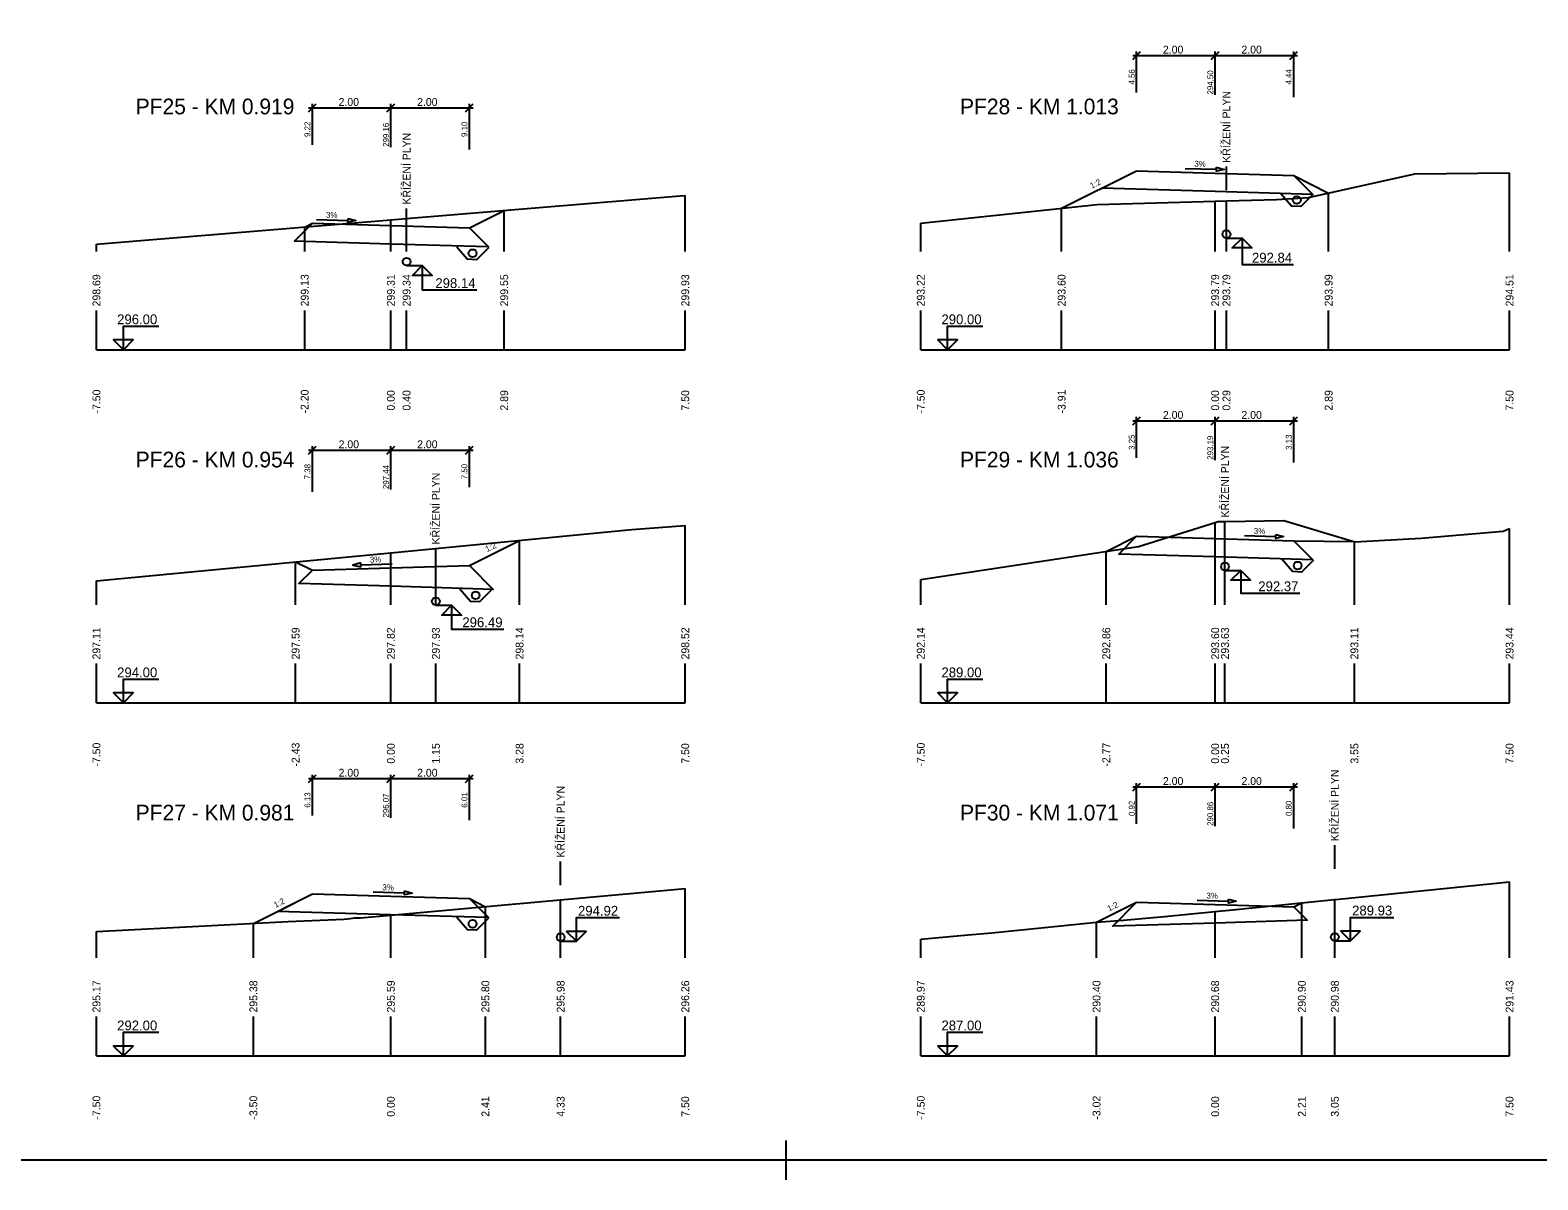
# Model space of a CAD drawing. Extents: x -9 to 2311, y -2 to 597.
# Drawn here: x 1693.1 to 2077.2, y -1.6 to 291.5 of the extents above; entities that cross this region are included whole.
import ezdxf

# ---------------------------------------------------------------- set-up
doc = ezdxf.new("R2010")
doc.units = 0
for name, color, linetype in [('KOTA', 7, 'Continuous'), ('KOTA_DELKY', 7, 'Continuous'), ('KOTA_DELKY_CONT', 7, 'Continuous'), ('KRIZENI', 7, 'Continuous'), ('NS_TELESO_VOZOVKY', 7, 'Continuous'), ('NS_V_PF', 7, 'Continuous'), ('POPISY_NAD_TERENEM', 7, 'Continuous'), ('REZY_PF_PUVODNI', 7, 'Continuous'), ('SESTAVY_REZU_PF', 7, 'Continuous'), ('SKLON', 7, 'Continuous'), ('SVK', 7, 'Continuous'), ('SVK_STAT', 7, 'Continuous')]:
    doc.layers.add(name, color=color, linetype=linetype)

msp = doc.modelspace()

# ---------------------------------------------------------------- linework, layer by layer
for p, q in [((1885.65, 8.39), (1885.65, -1.61)), ((1885.65, 8.39), (1885.65, -1.61)), ((1885.65, 8.39), (1885.65, -1.61)), ((1885.65, 8.39), (1885.65, -1.61)), ((1885.65, 8.39), (1885.65, -1.61)), ((1885.65, 8.39), (1885.65, -1.61)), ((1885.65, 8.39), (1885.65, -1.61)), ((1885.65, 8.39), (1885.65, -1.61)), ((1885.65, 8.39), (1885.65, -1.61)), ((1885.65, 8.39), (1885.65, -1.61)), ((1885.65, 8.39), (1885.65, -1.61)), ((1885.65, 8.39), (1885.65, -1.61)), ((1890.65, 3.39), (1880.65, 3.39)), ((1890.65, 3.39), (1880.65, 3.39)), ((1890.65, 3.39), (1880.65, 3.39)), ((1890.65, 3.39), (1880.65, 3.39)), ((1890.65, 3.39), (1880.65, 3.39)), ((1890.65, 3.39), (1880.65, 3.39)), ((1890.65, 3.39), (1880.65, 3.39)), ((1890.65, 3.39), (1880.65, 3.39)), ((1890.65, 3.39), (1880.65, 3.39)), ((1890.65, 3.39), (1880.65, 3.39)), ((1890.65, 3.39), (1880.65, 3.39)), ((1890.65, 3.39), (1880.65, 3.39))]:
    msp.add_line(p, q)
msp.add_lwpolyline([(-4.35, 597.39), (2305.65, 597.39), (2305.65, 3.39), (-4.35, 3.39)], close=True)
for points in [[(2019.85, 249.55), (2016.79, 246.51), (2014.45, 246.61), (2011.74, 249.75)], [(1809.88, 235.98), (1806.83, 232.94), (1804.48, 233.04), (1801.77, 236.18)], [(2020.07, 156.37), (2017.02, 153.33), (2014.67, 153.43), (2011.97, 156.57)], [(1810.66, 148.8), (1807.61, 145.76), (1805.26, 145.86), (1802.55, 149)], [(1809.89, 65.06), (1806.84, 62.03), (1804.49, 62.13), (1801.78, 65.26)]]:
    msp.add_lwpolyline(points)
for centre in [(2015.79, 248.15), (1805.82, 234.58), (2016.01, 154.97), (1806.6, 147.39), (1805.83, 63.66)]:
    msp.add_circle(centre, 1)
at = {"layer": 'KOTA'}
for points in [[(1997.87, 238.44), (2001.87, 238.44), (2004.37, 235.94), (2001.87, 235.94)], [(2001.87, 235.94), (1999.37, 235.94), (2001.87, 238.44), (2001.87, 231.71), (2014.96, 231.71)], [(1789.01, 231.44), (1793.01, 231.44), (1795.51, 228.94), (1793.01, 228.94)], [(1793.01, 228.94), (1790.51, 228.94), (1793.01, 231.44), (1793.01, 225.22), (1806.93, 225.22)], [(1716.85, 212.5), (1714.35, 212.5), (1716.85, 210), (1716.85, 216), (1725.85, 216)], [(1926.85, 212.5), (1924.35, 212.5), (1926.85, 210), (1926.85, 216), (1935.85, 216)], [(1716.85, 210), (1719.35, 212.5), (1716.85, 212.5)], [(1926.85, 210), (1929.35, 212.5), (1926.85, 212.5)], [(1997.5, 153.72), (2001.5, 153.72), (2004, 151.22), (2001.5, 151.22)], [(2001.5, 151.22), (1999, 151.22), (2001.5, 153.72), (2001.5, 147.95), (2016.58, 147.95)], [(1796.46, 144.86), (1800.46, 144.86), (1802.96, 142.36), (1800.46, 142.36)], [(1800.46, 142.36), (1797.96, 142.36), (1800.46, 144.86), (1800.46, 138.77), (1813.81, 138.77)], [(1716.85, 122.5), (1714.35, 122.5), (1716.85, 120), (1716.85, 126), (1725.85, 126)], [(1926.85, 122.5), (1924.35, 122.5), (1926.85, 120), (1926.85, 126), (1935.85, 126)], [(1716.85, 120), (1719.35, 122.5), (1716.85, 122.5)], [(1926.85, 120), (1929.35, 122.5), (1926.85, 122.5)], [(2029.48, 61.8), (2026.98, 61.8), (2029.48, 59.3), (2029.48, 65.3), (2040.48, 65.3)], [(2029.48, 61.8), (2026.98, 61.8), (2029.48, 59.3), (2029.48, 65.3), (2040.48, 65.3)], [(1828.26, 59.23), (1832.26, 59.23), (1834.76, 61.73), (1832.26, 61.73)], [(1828.26, 59.23), (1832.26, 59.23), (1834.76, 61.73), (1832.26, 61.73)], [(1832.26, 61.73), (1829.76, 61.73), (1832.26, 59.23), (1832.26, 65.23), (1843.26, 65.23)], [(1832.26, 61.73), (1829.76, 61.73), (1832.26, 59.23), (1832.26, 65.23), (1843.26, 65.23)], [(2025.48, 59.3), (2029.48, 59.3), (2031.98, 61.8), (2029.48, 61.8)], [(2025.48, 59.3), (2029.48, 59.3), (2031.98, 61.8), (2029.48, 61.8)], [(1716.85, 32.5), (1714.35, 32.5), (1716.85, 30), (1716.85, 36), (1725.85, 36)], [(1926.85, 32.5), (1924.35, 32.5), (1926.85, 30), (1926.85, 36), (1935.85, 36)], [(1716.85, 30), (1719.35, 32.5), (1716.85, 32.5)], [(1926.85, 30), (1929.35, 32.5), (1926.85, 32.5)]]:
    msp.add_lwpolyline(points, dxfattribs=at)
at = {"layer": 'KOTA_DELKY'}
for points in [[(1974, 284), (1976, 286)], [(1974, 285), (1996, 285)], [(1975, 275.6), (1975, 286)], [(1994, 284), (1996, 286)], [(1994, 284), (1996, 286)], [(1994, 285), (2016, 285)], [(1995, 275), (1995, 286)], [(1995, 275), (1995, 286)], [(2014, 284), (2016, 286)], [(2015, 274.4), (2015, 286)], [(1764, 270.64), (1766, 272.64)], [(1764, 271.64), (1786, 271.64)], [(1765, 262.24), (1765, 272.64)], [(1784, 270.64), (1786, 272.64)], [(1784, 270.64), (1786, 272.64)], [(1784, 271.64), (1806, 271.64)], [(1785, 261.64), (1785, 272.64)], [(1785, 261.64), (1785, 272.64)], [(1804, 270.64), (1806, 272.64)], [(1805, 261.04), (1805, 272.64)], [(1974, 190.88), (1976, 192.88)], [(1975, 182.48), (1975, 192.88)], [(1994, 190.88), (1996, 192.88)], [(1994, 190.88), (1996, 192.88)], [(1995, 181.88), (1995, 192.88)], [(1995, 181.88), (1995, 192.88)], [(2014, 190.88), (2016, 192.88)], [(2015, 181.28), (2015, 192.88)], [(1974, 191.88), (1996, 191.88)], [(1994, 191.88), (2016, 191.88)], [(1764, 183.39), (1766, 185.39)], [(1764, 184.39), (1786, 184.39)], [(1765, 173.79), (1765, 185.39)], [(1784, 183.39), (1786, 185.39)], [(1784, 183.39), (1786, 185.39)], [(1784, 184.39), (1806, 184.39)], [(1785, 174.39), (1785, 185.39)], [(1785, 174.39), (1785, 185.39)], [(1804, 183.39), (1806, 185.39)], [(1805, 174.99), (1805, 185.39)], [(1764, 99.67), (1766, 101.67)], [(1764, 100.67), (1786, 100.67)], [(1765, 91.27), (1765, 101.67)], [(1784, 99.67), (1786, 101.67)], [(1784, 99.67), (1786, 101.67)], [(1784, 100.67), (1806, 100.67)], [(1785, 90.67), (1785, 101.67)], [(1785, 90.67), (1785, 101.67)], [(1804, 99.67), (1806, 101.67)], [(1805, 90.07), (1805, 101.67)], [(1974, 97.55), (1976, 99.55)], [(1974, 98.55), (1996, 98.55)], [(1975, 89.15), (1975, 99.55)], [(1994, 97.55), (1996, 99.55)], [(1994, 97.55), (1996, 99.55)], [(1994, 98.55), (2016, 98.55)], [(1995, 88.55), (1995, 99.55)], [(1995, 88.55), (1995, 99.55)], [(2014, 97.55), (2016, 99.55)], [(2015, 87.95), (2015, 99.55)]]:
    msp.add_lwpolyline(points, dxfattribs=at)
at = {"layer": 'KRIZENI'}
for centre in [(1997.87, 239.44), (1789.01, 232.44), (1997.5, 154.72), (1796.46, 145.86), (1828.26, 60.23), (2025.48, 60.3)]:
    msp.add_circle(centre, 1, dxfattribs=at)
at = {"layer": 'NS_TELESO_VOZOVKY'}
for points in [[(1995, 255), (2015, 254.4), (2015, 254.4), (2019.85, 249.55), (1995, 250.3), (1966.13, 251.16), (1975, 255.6), (1975, 255.6), (1995, 255)], [(1785, 241.64), (1805, 241.04), (1805, 241.04), (1809.85, 236.2), (1785, 236.94), (1760.44, 237.68), (1765, 242.24), (1765, 242.24), (1785, 241.64)], [(1995, 161.88), (2015, 161.28), (2015, 161.28), (2019.85, 156.43), (1995, 157.18), (1970.44, 157.91), (1975, 162.48), (1975, 162.48), (1995, 161.88)], [(1785, 154.39), (1805, 154.99), (1805, 154.99), (1811.08, 148.91), (1785, 149.69), (1761.6, 150.39), (1765, 153.79), (1765, 153.79), (1785, 154.39)], [(1785, 70.67), (1805, 70.07), (1805, 70.07), (1809.85, 65.23), (1785, 65.97), (1756.13, 66.84), (1765, 71.27), (1765, 71.27), (1785, 70.67)], [(1995, 68.55), (2015, 67.95), (2015, 67.95), (2018.4, 64.56), (1995, 63.85), (1968.92, 63.07), (1975, 69.15), (1975, 69.15), (1995, 68.55)]]:
    msp.add_lwpolyline(points, dxfattribs=at)
at = {"layer": 'NS_V_PF'}
for points in [[(1955.88, 246.04), (1975, 255.6), (1975, 255.6), (1995, 255), (2015, 254.4), (2015, 254.4), (2023.91, 249.94)], [(1763.05, 241.27), (1765, 242.24), (1765, 242.24), (1785, 241.64), (1805, 241.04), (1805, 241.04), (1813.88, 245.48)], [(1760.73, 155.93), (1765, 153.79), (1765, 153.79), (1785, 154.39), (1805, 154.99), (1805, 154.99), (1817.79, 161.39)], [(1967.26, 158.6), (1975, 162.48), (1975, 162.48), (1995, 161.88), (2015, 161.28), (2015, 161.28), (2030.47, 161.07)], [(1749.98, 63.76), (1765, 71.27), (1765, 71.27), (1785, 70.67), (1805, 70.07), (1805, 70.07), (1809.09, 68.02)], [(1964.78, 64.04), (1975, 69.15), (1975, 69.15), (1995, 68.55), (2015, 67.95), (2015, 67.95), (2017.07, 68.99)]]:
    msp.add_lwpolyline(points, dxfattribs=at)
at = {"layer": 'POPISY_NAD_TERENEM'}
for points in [[(1997.87, 250.67), (1997.87, 256.67)], [(1789.01, 240), (1789.01, 246)], [(1997.5, 160.21), (1997.5, 166.21)], [(1796.46, 153.38), (1796.46, 159.38)], [(2025.48, 77.71), (2025.48, 83.71)], [(1828.26, 73.53), (1828.26, 79.53)]]:
    msp.add_lwpolyline(points, dxfattribs=at)
at = {"layer": 'REZY_PF_PUVODNI'}
for points in [[(1920, 242.22), (1964.95, 247), (1995, 247.86), (1997.85, 247.94), (2010.66, 248.31), (2018.79, 248.81), (2045.87, 254.8), (2070, 255.1)], [(1710, 236.87), (1785, 243.09), (1785, 243.09), (1788.93, 243.41), (1858.69, 249.2), (1860, 249.31)], [(1710, 151.07), (1785, 158.25), (1785, 158.25), (1796.34, 159.33), (1846.41, 164.13), (1860, 165.22)], [(1920, 151.42), (1975.45, 159.85), (1995, 165.99), (1995.73, 166.22), (1997.74, 166.25), (2012.51, 166.5), (2030.59, 161.04), (2047.52, 162), (2068.34, 163.77), (2070, 164.44)], [(1920, 59.71), (1925.51, 60.22), (1932.04, 60.83), (1938.14, 61.4), (1951.48, 62.72), (1964.8, 64.04), (1971.66, 64.62), (1982.09, 65.49), (1995, 66.78), (1995, 66.78), (1995.78, 66.86), (1998.55, 67.14), (2025.42, 69.82), (2026.47, 69.93), (2070, 74.33)], [(1710, 61.68), (1758.82, 64.22), (1773.1, 64.85), (1774.62, 65.01), (1775.79, 65.16), (1777.3, 65.17), (1785, 65.85), (1785, 65.85), (1785.01, 65.85), (1828.14, 69.74), (1860, 72.62)]]:
    msp.add_lwpolyline(points, dxfattribs=at)
at = {"layer": 'SESTAVY_REZU_PF'}
for points in [[(1710, 210), (1860, 210)], [(1920, 210), (2070, 210)], [(1710, 120), (1860, 120)], [(1920, 120), (2070, 120)], [(1710, 30), (1860, 30)], [(1920, 30), (2070, 30)]]:
    msp.add_lwpolyline(points, dxfattribs=at)
at = {"layer": 'SKLON'}
for points in [[(1987.32, 256.23), (1995.31, 255.99)], [(1995.33, 256.49), (1997.31, 255.93), (1995.3, 255.49), (1995.33, 256.49)], [(1766.09, 243.21), (1774.09, 242.97)], [(1774.1, 243.47), (1776.09, 242.91), (1774.07, 242.47), (1774.1, 243.47)], [(2002.45, 162.65), (2010.45, 162.41)], [(2010.47, 162.91), (2012.45, 162.35), (2010.44, 161.91), (2010.47, 162.91)], [(1777.32, 155.66), (1775.33, 155.1), (1777.35, 154.66), (1777.32, 155.66)], [(1777.33, 155.16), (1785.33, 155.4)], [(1780.47, 71.81), (1788.47, 71.57)], [(1788.48, 72.07), (1790.47, 71.51), (1788.45, 71.07), (1788.48, 72.07)], [(1990.38, 69.69), (1998.38, 69.45)], [(1998.39, 69.95), (2000.38, 69.39), (1998.36, 68.95), (1998.39, 69.95)]]:
    msp.add_lwpolyline(points, dxfattribs=at)
at = {"layer": 'SVK'}
for points in [[(2070, 235), (2070, 255.1)], [(2023.91, 235), (2023.91, 249.94)], [(1860, 235), (1860, 249.31)], [(1955.88, 235), (1955.88, 246.04)], [(1995, 235), (1995, 247.86)], [(1785, 235), (1785, 243.09)], [(1813.88, 235), (1813.88, 245.48)], [(1920, 235), (1920, 242.22)], [(1763.05, 235), (1763.05, 241.27)], [(1710, 235), (1710, 236.87)], [(1710, 210), (1710, 220)], [(1763.05, 210), (1763.05, 220)], [(1785, 210), (1785, 220)], [(1813.88, 210), (1813.88, 220)], [(1860, 210), (1860, 220)], [(1920, 210), (1920, 220)], [(1955.88, 210), (1955.88, 220)], [(1995, 210), (1995, 220)], [(2023.91, 210), (2023.91, 220)], [(2070, 210), (2070, 220)], [(1860, 145), (1860, 165.22)], [(1995, 145), (1995, 165.99)], [(1817.79, 145), (1817.79, 161.39)], [(2070, 145), (2070, 164.44)], [(1785, 145), (1785, 158.25)], [(1967.26, 145), (1967.26, 158.6)], [(2030.47, 145), (2030.47, 161.07)], [(1760.73, 145), (1760.73, 155.93)], [(1710, 145), (1710, 151.07)], [(1920, 145), (1920, 151.42)], [(1710, 120), (1710, 130)], [(1760.73, 120), (1760.73, 130)], [(1785, 120), (1785, 130)], [(1817.79, 120), (1817.79, 130)], [(1860, 120), (1860, 130)], [(1920, 120), (1920, 130)], [(1967.26, 120), (1967.26, 130)], [(1995, 120), (1995, 130)], [(2030.47, 120), (2030.47, 130)], [(2070, 120), (2070, 130)], [(2070, 55), (2070, 74.33)], [(1860, 55), (1860, 72.62)], [(1785, 55), (1785, 65.85)], [(1809.09, 55), (1809.09, 68.02)], [(1995, 55), (1995, 66.78)], [(2017.07, 55), (2017.07, 68.99)], [(1710, 55), (1710, 61.68)], [(1749.98, 55), (1749.98, 63.76)], [(1964.78, 55), (1964.78, 64.04)], [(1920, 55), (1920, 59.71)], [(1710, 30), (1710, 40)], [(1749.98, 30), (1749.98, 40)], [(1785, 30), (1785, 40)], [(1809.09, 30), (1809.09, 40)], [(1860, 30), (1860, 40)], [(1920, 30), (1920, 40)], [(1964.78, 30), (1964.78, 40)], [(1995, 30), (1995, 40)], [(2017.07, 30), (2017.07, 40)], [(2070, 30), (2070, 40)]]:
    msp.add_lwpolyline(points, dxfattribs=at)
at = {"layer": 'SVK_STAT'}
for points in [[(1997.87, 235), (1997.87, 247.94)], [(1789.01, 235), (1789.01, 243.42)], [(1789.01, 210), (1789.01, 220)], [(1997.87, 210), (1997.87, 220)], [(1997.5, 145), (1997.5, 146), (1997.5, 148), (1997.5, 166.25)], [(1796.46, 145), (1796.46, 159.35)], [(1796.46, 120), (1796.46, 130)], [(1997.5, 120), (1997.5, 124), (1997.5, 126), (1997.5, 130)], [(1828.26, 55), (1828.26, 69.75)], [(2025.48, 55), (2025.48, 69.83)], [(1828.26, 30), (1828.26, 40)], [(2025.48, 30), (2025.48, 40)]]:
    msp.add_lwpolyline(points, dxfattribs=at)

# ---------------------------------------------------------------- texts
at = {"layer": 'KOTA'}
for s, p in [('292.84', (2004.38, 232.21)), ('298.14', (1796.34, 225.72)), ('296.00', (1715.27, 216.5)), ('290.00', (1925.27, 216.5)), ('292.37', (2005.99, 148.45)), ('296.49', (1803.22, 139.27)), ('294.00', (1715.27, 126.5)), ('289.00', (1925.27, 126.5)), ('294.92', (1832.68, 65.73)), ('294.92', (1832.68, 65.73)), ('289.93', (2029.89, 65.8)), ('289.93', (2029.89, 65.8)), ('292.00', (1715.27, 36.5)), ('287.00', (1925.27, 36.5))]:
    msp.add_text(s, height=2.5, dxfattribs=at).set_placement(p)
at = {"layer": 'KOTA_DELKY'}
for p in [(1981.69, 285.5), (2001.69, 285.5), (1771.69, 272.14), (1791.69, 272.14), (1981.69, 192.38), (2001.69, 192.38), (1771.69, 184.89), (1791.69, 184.89), (1771.69, 101.17), (1791.69, 101.17), (1981.69, 99.05), (2001.69, 99.05)]:
    msp.add_text('2.00', height=2, dxfattribs=at).set_placement(p)
at = {"layer": 'KOTA_DELKY_CONT'}
for s, p in [('4.56', (1974.5, 277.59)), ('294.50', (1994.5, 275.07)), ('4.44', (2014.5, 277.59)), ('9.22', (1764.5, 264.23)), ('299.16', (1784.5, 261.72)), ('9.10', (1804.5, 264.23)), ('3.25', (1974.5, 184.47)), ('3.13', (2014.5, 184.47)), ('293.19', (1994.5, 181.95)), ('7.38', (1764.5, 176.98)), ('297.44', (1784.5, 174.47)), ('7.50', (1804.5, 176.98)), ('6.13', (1764.5, 93.26)), ('296.07', (1784.5, 90.75)), ('6.01', (1804.5, 93.26)), ('0.92', (1974.5, 91.14)), ('290.86', (1994.5, 88.63)), ('0.80', (2014.5, 91.14))]:
    msp.add_text(s, height=1.5, rotation=90, dxfattribs=at).set_placement(p)
at = {"layer": 'POPISY_NAD_TERENEM'}
for p in [(1998.87, 257.67), (1790.01, 247), (1998.5, 167.21), (1797.46, 160.38), (2026.48, 84.71), (1829.26, 80.53)]:
    msp.add_text('KŘÍŽENÍ PLYN', height=2, rotation=90, dxfattribs=at).set_placement(p)
at = {"layer": 'SESTAVY_REZU_PF'}
for s, p in [('PF25 - KM 0.919', (1720, 270)), ('PF28 - KM 1.013', (1930, 270)), ('PF26 - KM 0.954', (1720, 180)), ('PF29 - KM 1.036', (1930, 180)), ('PF27 - KM 0.981', (1720, 90)), ('PF30 - KM 1.071', (1930, 90))]:
    msp.add_text(s, height=4, dxfattribs=at).set_placement(p)
at = {"layer": 'SKLON'}
for s, rotation, p in [('3%', 358.2816, (1989.69, 256.66)), ('1:2', 26.5651, (1963.58, 251.01)), ('3%', 358.2816, (1768.47, 243.64)), ('3%', 358.2816, (2004.83, 163.08)), ('1:2', 26.5651, (1809.54, 158.38)), ('3%', 1.7184, (1779.67, 155.73)), ('3%', 358.2816, (1782.84, 72.24)), ('1:2', 26.5651, (1755.63, 67.71)), ('1:2', 26.5651, (1967.99, 66.77)), ('3%', 358.2816, (1992.76, 70.12))]:
    msp.add_text(s, height=1.5, rotation=rotation, dxfattribs=at).set_placement(p)
at = {"layer": 'SVK'}
for s, p in [(' 298.69', (1711, 220.3)), (' 299.13', (1764.05, 220.3)), (' 299.31', (1786, 220.3)), (' 299.55', (1814.88, 220.3)), (' 299.93', (1861, 220.3)), (' 293.22', (1921, 220.3)), (' 293.60', (1956.88, 220.3)), (' 293.79', (1996, 220.3)), (' 293.99', (2024.91, 220.3)), (' 294.51', (2071, 220.3)), (' -7.50', (1711, 193)), (' -2.20', (1764.05, 193)), (' -7.50', (1921, 193)), ('  0.00', (1786, 193)), ('  2.89', (1814.88, 193)), ('  7.50', (1861, 193)), (' -3.91', (1956.88, 193)), ('  0.00', (1996, 193)), ('  2.89', (2024.91, 193)), ('  7.50', (2071, 193)), (' 297.11', (1711, 130.3)), (' 297.59', (1761.73, 130.3)), (' 297.82', (1786, 130.3)), (' 298.14', (1818.79, 130.3)), (' 298.52', (1861, 130.3)), (' 292.14', (1921, 130.3)), (' 292.86', (1968.26, 130.3)), (' 293.60', (1996, 130.3)), (' 293.11', (2031.47, 130.3)), (' 293.44', (2071, 130.3)), (' -7.50', (1711, 103)), (' -2.43', (1761.73, 103)), ('  0.00', (1786, 103)), ('  3.28', (1818.79, 103)), ('  7.50', (1861, 103)), (' -7.50', (1921, 103)), (' -2.77', (1968.26, 103)), ('  0.00', (1996, 103)), ('  3.55', (2031.47, 103)), ('  7.50', (2071, 103)), (' 295.17', (1711, 40.3)), (' 295.38', (1750.98, 40.3)), (' 295.59', (1786, 40.3)), (' 295.80', (1810.09, 40.3)), (' 296.26', (1861, 40.3)), (' 289.97', (1921, 40.3)), (' 290.40', (1965.78, 40.3)), (' 290.68', (1996, 40.3)), (' 290.90', (2018.07, 40.3)), (' 291.43', (2071, 40.3)), (' -7.50', (1711, 13)), (' -3.50', (1750.98, 13)), ('  0.00', (1786, 13)), ('  2.41', (1810.09, 13)), ('  7.50', (1861, 13)), (' -7.50', (1921, 13)), (' -3.02', (1965.78, 13)), ('  0.00', (1996, 13)), ('  2.21', (2018.07, 13)), ('  7.50', (2071, 13))]:
    msp.add_text(s, height=2, rotation=90, dxfattribs=at).set_placement(p)
at = {"layer": 'SVK_STAT'}
for s, p in [(' 299.34', (1790.01, 220.3)), (' 293.79', (1998.87, 220.3)), ('  0.40', (1790.01, 193)), ('  0.29', (1998.87, 193)), (' 297.93', (1797.46, 130.3)), (' 293.63', (1998.5, 130.3)), ('  1.15', (1797.46, 103)), ('  0.25', (1998.5, 103)), (' 295.98', (1829.26, 40.3)), (' 290.98', (2026.48, 40.3)), ('  4.33', (1829.26, 13)), ('  3.05', (2026.48, 13))]:
    msp.add_text(s, height=2, rotation=90, dxfattribs=at).set_placement(p)

doc.saveas('drawing.dxf')
